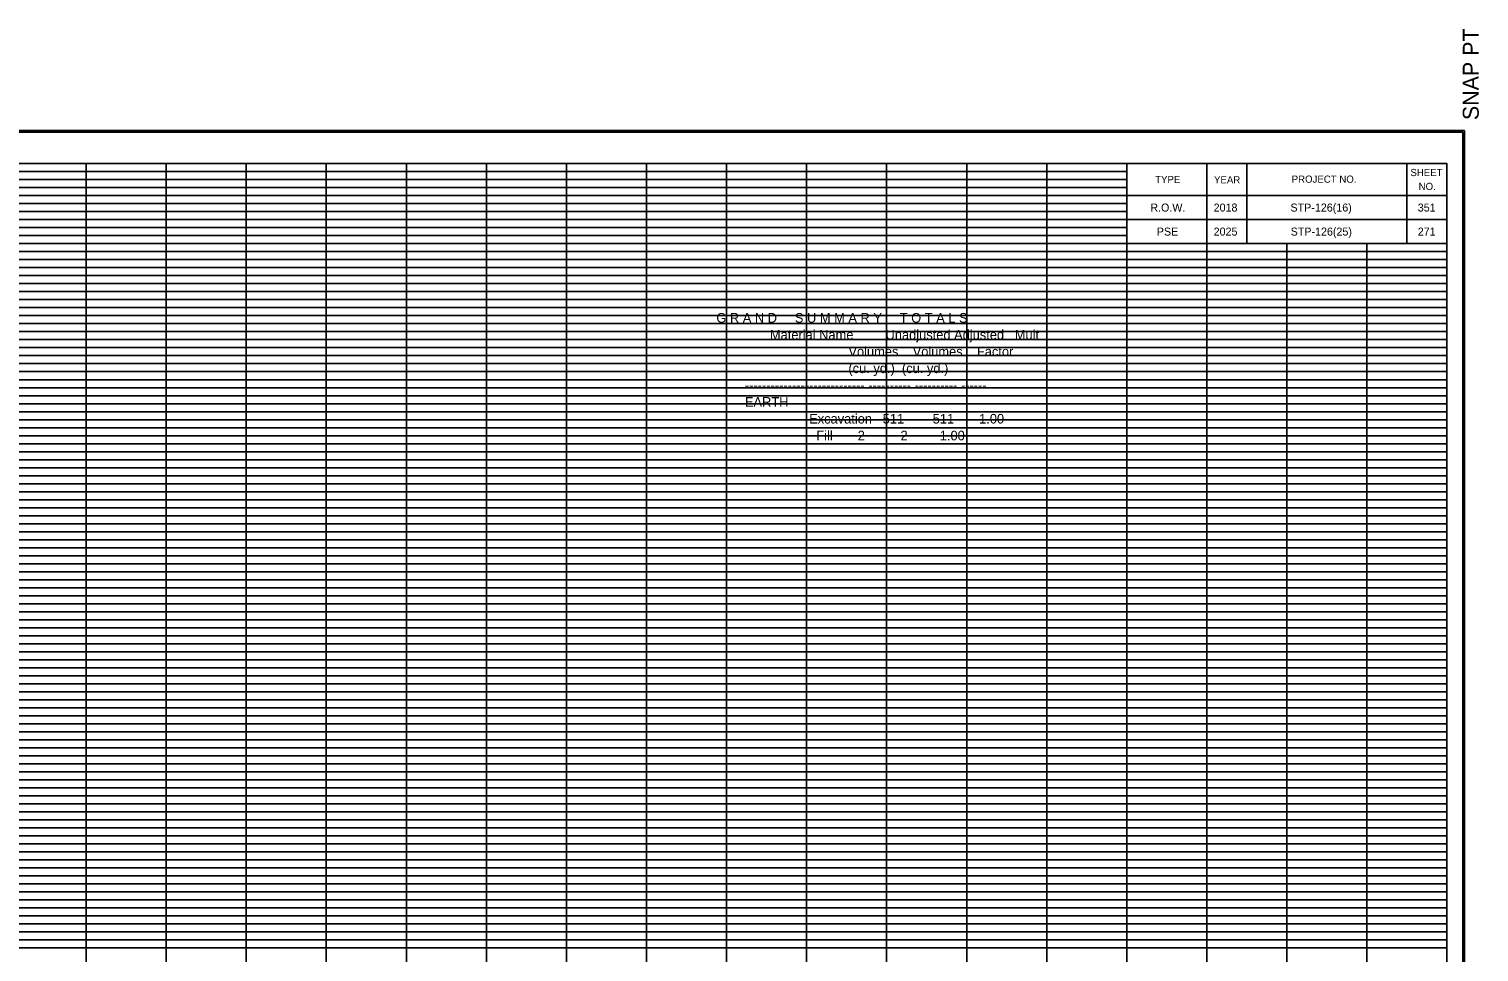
# Model space of a CAD drawing. Extents: x 130 to 1324, y -58 to 2657.
# Drawn here: x 1142.9 to 1324, y 1381.5 to 1496.8 of the extents above; entities that cross this region are included whole.
import ezdxf

# ---------------------------------------------------------------- set-up
doc = ezdxf.new("R2010")
doc.units = 0
for name, color, linetype in [('DESIGN - SCRATCH - User 1', 7, 'Continuous'), ('DESIGN - SHEET - Corner Text', 7, 'Continuous'), ('DESIGN - SHEET - Light Grid', 7, 'Continuous'), ('DESIGN - SHEET - Linework', 7, 'Continuous'), ('DESIGN - SHEET - Plot Shape', 7, 'Continuous'), ('DESIGN - TYPICAL - Finished Grade and Subgrade', 7, 'Continuous'), ('DESIGN - TYPICAL - Text', 7, 'Continuous')]:
    doc.layers.add(name, color=color, linetype=linetype)

# ---------------------------------------------------------------- blocks, each defined once
blk = doc.blocks.new('XSTSHT')
at = {"layer": 'DESIGN - SCRATCH - User 1'}
for p, q in [((28.5, 20.45), (28.5, 20.45)), ((29.24, 20.45), (29.24, 20.45)), ((30.49, 20.45), (30.49, 20.45)), ((31.74, 20.45), (31.74, 20.45)), ((28.5, 20.15), (28.5, 20.15)), ((29.24, 20.15), (29.24, 20.15)), ((30.49, 20.15), (30.49, 20.15)), ((31.74, 20.15), (31.74, 20.15))]:
    blk.add_line(p, q, dxfattribs=at)
at = {"layer": 'DESIGN - SHEET - Light Grid'}
for p, q in [((8, 20.9), (16, 20.9)), ((16, 20.9), (24, 20.9)), ((24, 20.9), (28, 20.9)), ((8, 20.8), (16, 20.8)), ((8, 20.7), (16, 20.7)), ((16, 20.8), (24, 20.8)), ((16, 20.7), (24, 20.7)), ((24, 20.8), (28, 20.8)), ((24, 20.7), (28, 20.7)), ((8, 20.6), (16, 20.6)), ((8, 20.5), (16, 20.5)), ((16, 20.6), (24, 20.6)), ((16, 20.5), (24, 20.5)), ((24, 20.6), (28, 20.6)), ((24, 20.5), (28, 20.5)), ((8, 20.4), (16, 20.4)), ((8, 20.3), (16, 20.3)), ((16, 20.4), (24, 20.4)), ((16, 20.3), (24, 20.3)), ((24, 20.4), (28, 20.4)), ((24, 20.3), (28, 20.3)), ((8, 20.2), (16, 20.2)), ((16, 20.2), (24, 20.2)), ((24, 20.2), (28, 20.2)), ((8, 20.1), (16, 20.1)), ((16, 20.1), (24, 20.1)), ((24, 20.1), (28, 20.1)), ((8, 19.9), (16, 19.9)), ((8, 19.8), (16, 19.8)), ((16, 19.9), (24, 19.9)), ((16, 19.8), (24, 19.8)), ((24, 19.9), (32, 19.9)), ((24, 19.8), (32, 19.8)), ((8, 19.7), (16, 19.7)), ((8, 19.6), (16, 19.6)), ((16, 19.7), (24, 19.7)), ((16, 19.6), (24, 19.6)), ((24, 19.7), (32, 19.7)), ((24, 19.6), (32, 19.6)), ((8, 19.5), (16, 19.5)), ((8, 19.4), (16, 19.4)), ((16, 19.5), (24, 19.5)), ((16, 19.4), (24, 19.4)), ((24, 19.5), (32, 19.5)), ((24, 19.4), (32, 19.4)), ((8, 19.3), (16, 19.3)), ((16, 19.3), (24, 19.3)), ((24, 19.3), (32, 19.3)), ((8, 19.2), (16, 19.2)), ((8, 19.1), (16, 19.1)), ((16, 19.2), (24, 19.2)), ((16, 19.1), (24, 19.1)), ((24, 19.2), (32, 19.2)), ((24, 19.1), (32, 19.1)), ((8, 18.9), (16, 18.9)), ((16, 18.9), (24, 18.9)), ((24, 18.9), (32, 18.9)), ((8, 18.8), (16, 18.8)), ((8, 18.7), (16, 18.7)), ((16, 18.8), (24, 18.8)), ((16, 18.7), (24, 18.7)), ((24, 18.8), (32, 18.8)), ((24, 18.7), (32, 18.7)), ((8, 18.6), (16, 18.6)), ((8, 18.5), (16, 18.5)), ((16, 18.6), (24, 18.6)), ((16, 18.5), (24, 18.5)), ((24, 18.6), (32, 18.6)), ((24, 18.5), (32, 18.5)), ((8, 18.4), (16, 18.4)), ((8, 18.3), (16, 18.3)), ((16, 18.4), (24, 18.4)), ((16, 18.3), (24, 18.3)), ((24, 18.4), (32, 18.4)), ((24, 18.3), (32, 18.3)), ((8, 18.2), (16, 18.2)), ((16, 18.2), (24, 18.2)), ((24, 18.2), (32, 18.2)), ((8, 18.1), (16, 18.1)), ((16, 18.1), (24, 18.1)), ((24, 18.1), (32, 18.1)), ((8, 17.9), (16, 17.9)), ((8, 17.8), (16, 17.8)), ((16, 17.9), (24, 17.9)), ((16, 17.8), (24, 17.8)), ((24, 17.9), (32, 17.9)), ((24, 17.8), (32, 17.8)), ((8, 17.7), (16, 17.7)), ((8, 17.6), (16, 17.6)), ((16, 17.7), (24, 17.7)), ((16, 17.6), (24, 17.6)), ((24, 17.7), (32, 17.7)), ((24, 17.6), (32, 17.6)), ((8, 17.5), (16, 17.5)), ((8, 17.4), (16, 17.4)), ((16, 17.5), (24, 17.5)), ((16, 17.4), (24, 17.4)), ((24, 17.5), (32, 17.5)), ((24, 17.4), (32, 17.4)), ((8, 17.3), (16, 17.3)), ((16, 17.3), (24, 17.3)), ((24, 17.3), (32, 17.3)), ((8, 17.2), (16, 17.2)), ((8, 17.1), (16, 17.1)), ((16, 17.2), (24, 17.2)), ((16, 17.1), (24, 17.1)), ((24, 17.2), (32, 17.2)), ((24, 17.1), (32, 17.1)), ((8, 16.9), (16, 16.9)), ((16, 16.9), (24, 16.9)), ((24, 16.9), (32, 16.9)), ((8, 16.8), (16, 16.8)), ((8, 16.7), (16, 16.7)), ((16, 16.8), (24, 16.8)), ((16, 16.7), (24, 16.7)), ((24, 16.8), (32, 16.8)), ((24, 16.7), (32, 16.7)), ((8, 16.6), (16, 16.6)), ((8, 16.5), (16, 16.5)), ((16, 16.6), (24, 16.6)), ((16, 16.5), (24, 16.5)), ((24, 16.6), (32, 16.6)), ((24, 16.5), (32, 16.5)), ((8, 16.4), (16, 16.4)), ((16, 16.4), (24, 16.4)), ((24, 16.4), (32, 16.4)), ((8, 16.3), (16, 16.3)), ((8, 16.2), (16, 16.2)), ((16, 16.3), (24, 16.3)), ((16, 16.2), (24, 16.2)), ((24, 16.3), (32, 16.3)), ((24, 16.2), (32, 16.2)), ((8, 16.1), (16, 16.1)), ((16, 16.1), (24, 16.1)), ((24, 16.1), (32, 16.1)), ((8, 15.9), (16, 15.9)), ((8, 15.8), (16, 15.8)), ((16, 15.9), (24, 15.9)), ((16, 15.8), (24, 15.8)), ((24, 15.9), (32, 15.9)), ((24, 15.8), (32, 15.8)), ((8, 15.7), (16, 15.7)), ((8, 15.6), (16, 15.6)), ((16, 15.7), (24, 15.7)), ((16, 15.6), (24, 15.6)), ((24, 15.7), (32, 15.7)), ((24, 15.6), (32, 15.6)), ((8, 15.5), (16, 15.5)), ((8, 15.4), (16, 15.4)), ((16, 15.5), (24, 15.5)), ((16, 15.4), (24, 15.4)), ((24, 15.5), (32, 15.5)), ((24, 15.4), (32, 15.4)), ((8, 15.3), (16, 15.3)), ((16, 15.3), (24, 15.3)), ((24, 15.3), (32, 15.3)), ((8, 15.2), (16, 15.2)), ((8, 15.1), (16, 15.1)), ((16, 15.2), (24, 15.2)), ((16, 15.1), (24, 15.1)), ((24, 15.2), (32, 15.2)), ((24, 15.1), (32, 15.1)), ((8, 14.9), (16, 14.9)), ((16, 14.9), (24, 14.9)), ((24, 14.9), (32, 14.9)), ((8, 14.8), (16, 14.8)), ((8, 14.7), (16, 14.7)), ((16, 14.8), (24, 14.8)), ((16, 14.7), (24, 14.7)), ((24, 14.8), (32, 14.8)), ((24, 14.7), (32, 14.7)), ((8, 14.6), (16, 14.6)), ((8, 14.5), (16, 14.5)), ((16, 14.6), (24, 14.6)), ((16, 14.5), (24, 14.5)), ((24, 14.6), (32, 14.6)), ((24, 14.5), (32, 14.5)), ((8, 14.4), (16, 14.4)), ((16, 14.4), (24, 14.4)), ((24, 14.4), (32, 14.4)), ((8, 14.3), (16, 14.3)), ((8, 14.2), (16, 14.2)), ((16, 14.3), (24, 14.3)), ((16, 14.2), (24, 14.2)), ((24, 14.3), (32, 14.3)), ((24, 14.2), (32, 14.2)), ((8, 14.1), (16, 14.1)), ((16, 14.1), (24, 14.1)), ((24, 14.1), (32, 14.1)), ((8, 13.9), (16, 13.9)), ((8, 13.8), (16, 13.8)), ((16, 13.9), (24, 13.9)), ((16, 13.8), (24, 13.8)), ((24, 13.9), (32, 13.9)), ((24, 13.8), (32, 13.8)), ((8, 13.7), (16, 13.7)), ((8, 13.6), (16, 13.6)), ((16, 13.7), (24, 13.7)), ((16, 13.6), (24, 13.6)), ((24, 13.7), (32, 13.7)), ((24, 13.6), (32, 13.6)), ((8, 13.5), (16, 13.5)), ((16, 13.5), (24, 13.5)), ((24, 13.5), (32, 13.5)), ((8, 13.4), (16, 13.4)), ((8, 13.3), (16, 13.3)), ((16, 13.4), (24, 13.4)), ((16, 13.3), (24, 13.3)), ((24, 13.4), (32, 13.4)), ((24, 13.3), (32, 13.3)), ((8, 13.2), (16, 13.2)), ((8, 13.1), (16, 13.1)), ((16, 13.2), (24, 13.2)), ((16, 13.1), (24, 13.1)), ((24, 13.2), (32, 13.2)), ((24, 13.1), (32, 13.1)), ((8, 12.9), (16, 12.9)), ((16, 12.9), (24, 12.9)), ((24, 12.9), (32, 12.9)), ((8, 12.8), (16, 12.8)), ((8, 12.7), (16, 12.7)), ((16, 12.8), (24, 12.8)), ((16, 12.7), (24, 12.7)), ((24, 12.8), (32, 12.8)), ((24, 12.7), (32, 12.7)), ((8, 12.6), (16, 12.6)), ((8, 12.5), (16, 12.5)), ((16, 12.6), (24, 12.6)), ((16, 12.5), (24, 12.5)), ((24, 12.6), (32, 12.6)), ((24, 12.5), (32, 12.5)), ((8, 12.4), (16, 12.4)), ((16, 12.4), (24, 12.4)), ((24, 12.4), (32, 12.4)), ((8, 12.3), (16, 12.3)), ((8, 12.2), (16, 12.2)), ((16, 12.3), (24, 12.3)), ((16, 12.2), (24, 12.2)), ((24, 12.3), (32, 12.3)), ((24, 12.2), (32, 12.2)), ((8, 12.1), (16, 12.1)), ((16, 12.1), (24, 12.1)), ((24, 12.1), (32, 12.1)), ((8, 11.9), (16, 11.9)), ((8, 11.8), (16, 11.8)), ((16, 11.9), (24, 11.9)), ((16, 11.8), (24, 11.8)), ((24, 11.9), (32, 11.9)), ((24, 11.8), (32, 11.8)), ((8, 11.7), (16, 11.7)), ((8, 11.6), (16, 11.6)), ((16, 11.7), (24, 11.7)), ((16, 11.6), (24, 11.6)), ((24, 11.7), (32, 11.7)), ((24, 11.6), (32, 11.6)), ((8, 11.5), (16, 11.5)), ((16, 11.5), (24, 11.5)), ((24, 11.5), (32, 11.5)), ((8, 11.4), (16, 11.4)), ((8, 11.3), (16, 11.3)), ((16, 11.4), (24, 11.4)), ((16, 11.3), (24, 11.3)), ((24, 11.4), (32, 11.4)), ((24, 11.3), (32, 11.3)), ((8, 11.2), (16, 11.2)), ((16, 11.2), (24, 11.2)), ((24, 11.2), (32, 11.2))]:
    blk.add_line(p, q, dxfattribs=at)
at = {"layer": 'DESIGN - SHEET - Linework'}
for p, q in [((-1.823, 21.414), (32.217, 21.414)), ((32.217, 21.414), (32.217, -0.414)), ((15, 0), (15, 21)), ((16, 0), (16, 21)), ((17, 0), (17, 21)), ((18, 0), (18, 21)), ((19, 0), (19, 21)), ((20, 0), (20, 21)), ((21, 0), (21, 21)), ((22, 0), (22, 21)), ((23, 0), (23, 21)), ((24, 0), (24, 21)), ((25, 0), (25, 21)), ((26, 0), (26, 21)), ((27, 0), (27, 21)), ((0, 20), (28, 20)), ((28, 0), (28, 20)), ((29, 0), (29, 20)), ((30, 0), (30, 20)), ((31, 0), (31, 20)), ((0, 19), (32, 19)), ((0, 18), (32, 18)), ((0, 17), (32, 17)), ((0, 16), (32, 16)), ((0, 15), (32, 15)), ((0, 14), (32, 14)), ((0, 13), (32, 13)), ((0, 12), (32, 12))]:
    blk.add_line(p, q, dxfattribs=at)
for points in [[(0, 21), (0, 0), (32, 0), (32, 21), (0, 21)], [(28, 21), (28, 20), (32, 20), (32, 21), (31.5, 21), (31.5, 20), (29.5, 20), (29.5, 21), (29, 21), (29, 20), (32, 20), (28, 20), (28, 20.3), (32, 20.3), (32, 20.6), (28, 20.6)]]:
    blk.add_lwpolyline(points, dxfattribs=at)
at = {"layer": 'DESIGN - SHEET - Plot Shape'}
for points in [[(-1.803, 21.394), (32.197, 21.394), (32.197, -0.394), (-1.803, -0.394)], [(-0.85, 21), (32, 21), (32, -0.25), (-0.85, -0.25)]]:
    blk.add_lwpolyline(points, close=True, dxfattribs=at)
at = {"layer": 'DESIGN - SHEET - Corner Text'}
blk.add_text('  SNAP PT', height=0.2, rotation=90, dxfattribs=at).set_placement((32.397, 21.394))
for s, p in [('TYPE', (28.354, 20.756)), ('YEAR', (29.09, 20.752)), ('PROJECT NO.', (30.06, 20.76)), ('SHEET', (31.543, 20.843)), ('NO.', (31.646, 20.669))]:
    blk.add_text(s, height=0.09, dxfattribs=at).set_placement(p)

msp = doc.modelspace()

# ---------------------------------------------------------------- linework, layer by layer
at = {"layer": 'DESIGN - SHEET - Plot Shape'}
msp.add_lwpolyline([(991.5, 1267.5), (1320, 1267.5), (1320, 1480), (991.5, 1480)], close=True, dxfattribs=at)

# ---------------------------------------------------------------- block references
at = {"layer": 'DESIGN - TYPICAL - Finished Grade and Subgrade', "xscale": 10, "yscale": 10}
msp.add_blockref('XSTSHT', (1000, 1270), dxfattribs=at)

# ---------------------------------------------------------------- texts
at = {"layer": 'DESIGN - SHEET - Corner Text'}
for s, p in [('R.O.W.', (1282.94, 1474)), ('2018', (1290.85, 1474)), ('STP-126(16)', (1300.45, 1474)), ('351', (1316.35, 1474)), ('PSE', (1283.75, 1471)), ('2025', (1290.85, 1471)), ('STP-126(25)', (1300.47, 1471)), ('271', (1316.35, 1471))]:
    msp.add_text(s, height=1, dxfattribs=at).set_placement(p)
at = {"layer": 'DESIGN - TYPICAL - Text'}
for s, p in [('G R A N D     S U M M A R Y     T O T A L S', (1228.73, 1460.12)), ('               Material Name         Unadjusted Adjusted   Mult', (1228.73, 1458.02)), ('                                     Volumes    Volumes    Factor', (1228.73, 1455.92)), ('                                     (cu. yd.)  (cu. yd.)', (1228.73, 1453.82)), ('        ---------------------------- ---------- ---------- ------', (1228.73, 1451.72)), ('        EARTH', (1228.73, 1449.62)), ('                          Excavation   511        511       1.00', (1228.73, 1447.52)), ('                            Fill       2          2         1.00', (1228.73, 1445.42))]:
    msp.add_text(s, height=1.2, dxfattribs=at).set_placement(p)

doc.saveas('drawing.dxf')
